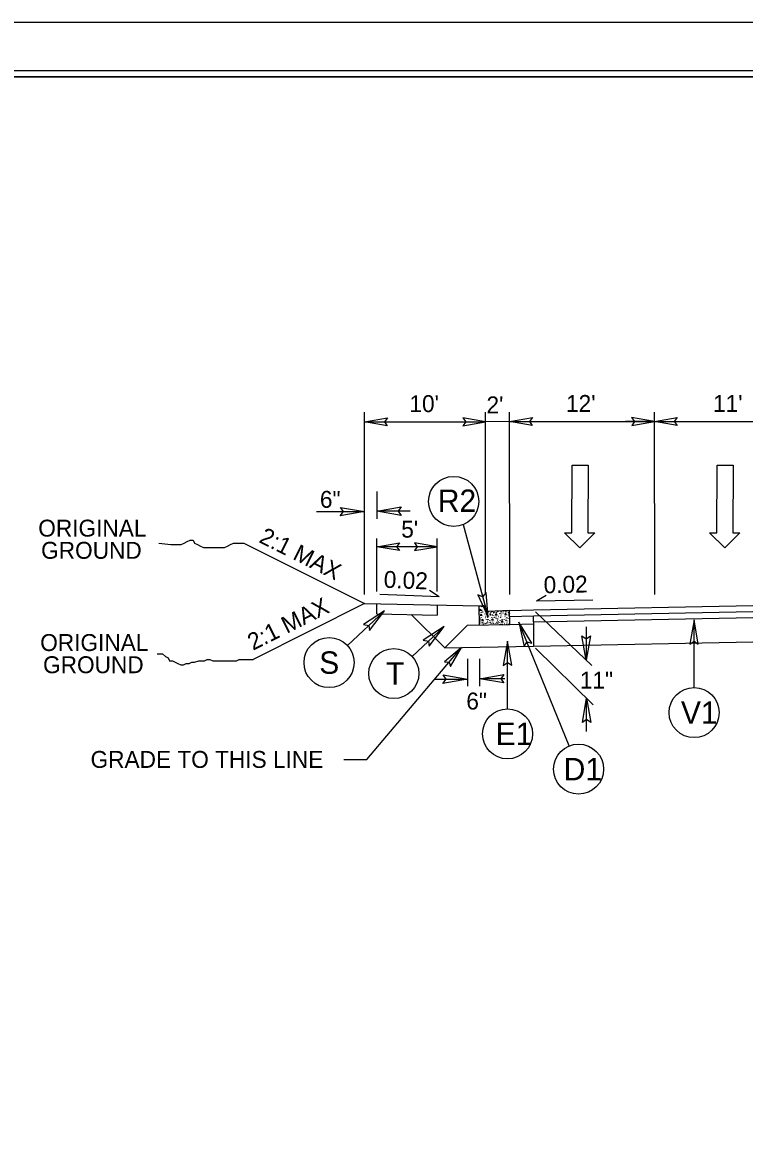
# Model space of a CAD drawing. Extents: x 1640342 to 1730599, y 538663 to 843747.
# Drawn here: x 1729954.3 to 1730014, y 539037.8 to 539130.9 of the extents above; entities that cross this region are included whole.
import ezdxf

# ---------------------------------------------------------------- set-up
doc = ezdxf.new("R2010")
doc.units = 0
for name, color, linetype in [('Default', 7, 'Continuous'), ('Prop Terminator CELL', 7, 'Continuous'), ('Sheet Clip Boundary CELL', 7, 'Continuous'), ('Sheet Layout Plan Border', 7, 'Continuous'), ('Sheet Plan CELL', 7, 'Continuous'), ('Sheet Plan Layout CELL', 7, 'Continuous'), ('Sheet Plot Border Inside CELL', 7, 'Continuous'), ('Sheet Plot Border Outside CELL', 7, 'Continuous'), ('Typical Curb CELL', 7, 'Continuous'), ('Typical Hinge Slope Arterial CELL', 7, 'Continuous'), ('Typical Hinge Slope Interstate CELL', 7, 'Continuous'), ('Typical ID Circle CELL', 7, 'Continuous'), ('Typical Pavement Slope CELL', 7, 'Continuous'), ('Typical Pavement Slope Information CELL', 7, 'Continuous'), ('Typical Shoulder Slope CELL', 7, 'Continuous'), ('Typical Terminator CELL', 7, 'Continuous'), ('Typical Text General CELL', 7, 'Continuous'), ('Typical Text ID Circle CELL', 7, 'Continuous')]:
    doc.layers.add(name, color=color, linetype=linetype)

msp = doc.modelspace()

# ---------------------------------------------------------------- linework, layer by layer
at = {"layer": 'Default'}
for p, q in [((1729982.603, 539083.581), (1729982.603, 539098.671)), ((1729992.603, 539083.581), (1729992.603, 539098.671)), ((1729994.596, 539083.581), (1729994.581, 539098.671)), ((1730006.552, 539098.671), (1730006.567, 539083.593)), ((1729982.603, 539097.882), (1729992.604, 539097.882)), ((1729994.582, 539097.895), (1729992.604, 539097.882)), ((1730006.553, 539097.895), (1730017.553, 539097.906)), ((1729999.724, 539088.703), (1729999.754, 539094.299)), ((1729999.754, 539094.299), (1730001.073, 539094.292)), ((1730001.073, 539094.292), (1730001.043, 539088.696)), ((1730011.71, 539088.703), (1730011.74, 539094.299)), ((1730011.74, 539094.299), (1730013.059, 539094.292)), ((1730013.059, 539094.292), (1730013.029, 539088.696)), ((1729983.603, 539092.116), (1729983.603, 539089.856)), ((1729978.634, 539090.452), (1729982.603, 539090.452)), ((1729986.353, 539090.475), (1729983.603, 539090.475)), ((1729983.603, 539083.835), (1729983.603, 539088.237)), ((1729988.603, 539083.835), (1729988.603, 539088.237)), ((1730000.397, 539087.44), (1729999.125, 539088.706)), ((1729999.125, 539088.706), (1729999.724, 539088.703)), ((1730001.643, 539088.693), (1730000.397, 539087.44)), ((1730001.043, 539088.696), (1730001.643, 539088.693)), ((1730012.382, 539087.44), (1730011.11, 539088.706)), ((1730011.11, 539088.706), (1730011.71, 539088.703)), ((1730013.628, 539088.693), (1730012.382, 539087.44)), ((1730013.029, 539088.696), (1730013.628, 539088.693)), ((1729988.603, 539087.541), (1729983.603, 539087.541)), ((1729996.74, 539082.16), (1730001.395, 539077.704)), ((1730000.926, 539080.902), (1730000.926, 539078.152)), ((1729996.74, 539079.16), (1730001.502, 539074.467)), ((1729991.095, 539078.261), (1729991.095, 539076.001)), ((1729992.095, 539078.261), (1729992.095, 539076.001)), ((1729988.364, 539076.597), (1729991.095, 539076.597)), ((1729994.195, 539076.62), (1729992.095, 539076.62)), ((1730000.95, 539072.261), (1730000.95, 539075.011))]:
    msp.add_line(p, q, dxfattribs=at)
for points in [[(1729984.477, 539097.559), (1729982.603, 539097.882), (1729984.487, 539098.215), (1729984.248, 539097.882)], [(1729990.729, 539097.559), (1729992.604, 539097.882), (1729990.719, 539098.215), (1729990.958, 539097.882)], [(1729996.456, 539097.572), (1729994.582, 539097.895), (1729996.466, 539098.228), (1729996.227, 539097.895)], [(1730004.679, 539097.572), (1730006.553, 539097.895), (1730004.668, 539098.228), (1730004.908, 539097.895)], [(1730008.427, 539097.572), (1730006.553, 539097.895), (1730008.437, 539098.228), (1730008.198, 539097.895)], [(1729985.477, 539087.218), (1729983.603, 539087.541), (1729985.487, 539087.874), (1729985.248, 539087.541)], [(1729986.728, 539087.218), (1729988.603, 539087.541), (1729986.718, 539087.874), (1729986.957, 539087.541)]]:
    msp.add_lwpolyline(points, close=True, dxfattribs=at)
msp.add_lwpolyline([(1729994.582, 539097.895), (1730006.553, 539097.895), (1730004.181, 539097.905)], dxfattribs=at)
at = {"layer": 'Prop Terminator CELL'}
msp.add_lwpolyline([(1729989.693, 539077.625), (1729990.619, 539079.2), (1729989.205, 539078.024), (1729989.598, 539077.993)], close=True, dxfattribs=at)
at = {"layer": 'Sheet Clip Boundary CELL'}
msp.add_lwpolyline([(1729883.99, 538916.418), (1730163.993, 538916.418), (1730163.993, 539084.12), (1730126.14, 539084.12), (1730126.14, 539126.418), (1729883.99, 539126.418)], close=True, dxfattribs=at)
at = {"layer": 'Sheet Layout Plan Border'}
msp.add_lwpolyline([(1729883.99, 538916.418), (1730163.993, 538916.418), (1730163.993, 539084.12), (1730126.14, 539084.12), (1730126.14, 539126.418), (1729883.99, 539126.418)], close=True, dxfattribs=at)
at = {"layer": 'Sheet Plan CELL'}
for points in [[(1729873.99, 538916.418), (1729873.985, 539126.413), (1730133.983, 539126.42), (1730133.985, 539096.408), (1730173.993, 539096.405), (1730173.993, 538916.418)], [(1730173.998, 539126.418), (1729873.99, 539126.418), (1729873.99, 538916.418), (1730173.993, 538916.418)]]:
    msp.add_lwpolyline(points, close=True, dxfattribs=at)
at = {"layer": 'Sheet Plan Layout CELL'}
msp.add_lwpolyline([(1729873.985, 539126.413), (1729873.99, 538916.418), (1730173.99, 538916.418), (1730173.99, 539084.12), (1730126.14, 539084.12), (1730126.14, 539126.418)], close=True, dxfattribs=at)
at = {"layer": 'Sheet Plot Border Inside CELL'}
msp.add_lwpolyline([(1729843.293, 538915.915), (1730176.49, 538915.918), (1730176.493, 539126.915), (1729843.293, 539126.915)], close=True, dxfattribs=at)
at = {"layer": 'Sheet Plot Border Outside CELL'}
msp.add_lwpolyline([(1729840.693, 538911.915), (1730177.393, 538911.915), (1730177.393, 539130.915), (1729840.693, 539130.915)], close=True, dxfattribs=at)
at = {"layer": 'Typical Curb CELL'}
for p, q in [((1729992.071, 539082.657), (1729992.331, 539082.661)), ((1729992.095, 539081.063), (1729992.071, 539082.657)), ((1729992.113, 539082.279), (1729992.266, 539082.326)), ((1729992.251, 539082.236), (1729992.113, 539082.279)), ((1729992.244, 539081.963), (1729992.142, 539081.886)), ((1729992.142, 539081.886), (1729992.308, 539081.849)), ((1729992.308, 539081.849), (1729992.244, 539081.963)), ((1729992.266, 539082.326), (1729992.251, 539082.236)), ((1729992.574, 539082.414), (1729992.574, 539082.425)), ((1729994.574, 539082.279), (1729992.827, 539082.179)), ((1729992.984, 539082.03), (1729992.951, 539081.917)), ((1729992.951, 539081.917), (1729993.071, 539081.912)), ((1729993.071, 539081.912), (1729992.984, 539082.03)), ((1729993.491, 539081.982), (1729993.389, 539081.906)), ((1729993.389, 539081.906), (1729993.555, 539081.869)), ((1729993.555, 539081.869), (1729993.491, 539081.982)), ((1729994.231, 539082.05), (1729994.199, 539081.936)), ((1729994.199, 539081.936), (1729994.32, 539081.931)), ((1729994.32, 539081.931), (1729994.231, 539082.05)), ((1729994.592, 539081.113), (1729994.574, 539082.279)), ((1729992.377, 539081.514), (1729992.275, 539081.437)), ((1729992.275, 539081.437), (1729992.441, 539081.4)), ((1729992.441, 539081.4), (1729992.377, 539081.514)), ((1729993.182, 539081.57), (1729993.08, 539081.493)), ((1729993.08, 539081.493), (1729993.246, 539081.456)), ((1729993.246, 539081.456), (1729993.182, 539081.57)), ((1729993.988, 539081.401), (1729993.886, 539081.325)), ((1729993.886, 539081.325), (1729994.052, 539081.288)), ((1729994.052, 539081.288), (1729993.988, 539081.401))]:
    msp.add_line(p, q, dxfattribs=at)
for centre in [(1729992.086, 539082.547), (1729992.14, 539082.365), (1729992.23, 539081.706), (1729992.241, 539082.094), (1729992.302, 539082.584), (1729992.36, 539082.146), (1729992.4, 539081.748), (1729992.539, 539081.984), (1729992.578, 539081.688), (1729992.616, 539082.179), (1729992.633, 539081.803), (1729992.634, 539082.128), (1729992.665, 539081.958), (1729992.749, 539081.719), (1729992.812, 539082.046), (1729992.839, 539082.148), (1729992.954, 539081.745), (1729993.034, 539082.112), (1729993.114, 539081.679), (1729993.13, 539082.167), (1729993.162, 539081.914), (1729993.24, 539082.075), (1729993.259, 539081.87), (1729993.295, 539082.11), (1729993.314, 539082.013), (1729993.324, 539081.705), (1729993.478, 539081.725), (1729993.489, 539082.113), (1729993.608, 539082.165), (1729993.648, 539081.767), (1729993.787, 539082.003), (1729993.826, 539081.707), (1729993.864, 539082.198), (1729993.881, 539081.822), (1729993.882, 539082.148), (1729993.913, 539081.977), (1729993.997, 539081.739), (1729994.06, 539082.065), (1729994.087, 539082.167), (1729994.202, 539081.765), (1729994.234, 539082.232), (1729994.282, 539082.131), (1729994.362, 539081.699), (1729994.377, 539082.217), (1729994.41, 539081.933), (1729994.488, 539082.094), (1729994.507, 539081.889), (1729994.543, 539082.129), (1729994.562, 539082.033), (1729994.572, 539081.725), (1729992.144, 539081.401), (1729992.199, 539081.545), (1729992.209, 539081.237), (1729992.363, 539081.257), (1729992.409, 539081.145), (1729992.534, 539081.299), (1729992.58, 539081.176), (1729992.672, 539081.535), (1729992.711, 539081.239), (1729992.767, 539081.354), (1729992.798, 539081.508), (1729992.882, 539081.27), (1729992.95, 539081.458), (1729993.004, 539081.601), (1729993.015, 539081.293), (1729993.065, 539081.173), (1729993.169, 539081.313), (1729993.236, 539081.204), (1729993.339, 539081.355), (1729993.449, 539081.173), (1729993.478, 539081.591), (1729993.517, 539081.295), (1729993.572, 539081.41), (1729993.604, 539081.565), (1729993.62, 539081.204), (1729993.688, 539081.326), (1729993.755, 539081.289), (1729993.81, 539081.433), (1729993.821, 539081.125), (1729993.964, 539081.501), (1729993.974, 539081.144), (1729994.135, 539081.532), (1729994.145, 539081.187), (1729994.284, 539081.423), (1729994.302, 539081.566), (1729994.323, 539081.127), (1729994.378, 539081.242), (1729994.41, 539081.396), (1729994.472, 539081.598), (1729994.493, 539081.158)]:
    msp.add_circle(centre, 0.00801, dxfattribs=at)
for centre, start, end in [((1729992.334, 539082.421), 0.8814, 90.8814), ((1729992.813, 539082.418), 180.8814, 273.26586)]:
    msp.add_arc(centre, 0.239, start, end, dxfattribs=at)
at = {"layer": 'Typical Hinge Slope Arterial CELL'}
for p, q in [((1729972.61, 539087.842), (1729982.603, 539082.846)), ((1729982.603, 539082.846), (1729973.386, 539078.223))]:
    msp.add_line(p, q, dxfattribs=at)
msp.add_lwpolyline([(1729965.593, 539087.842), (1729966.577, 539087.72), (1729966.824, 539087.72), (1729967.193, 539087.72), (1729967.439, 539087.72), (1729967.686, 539087.842), (1729967.932, 539087.966), (1729968.178, 539088.089), (1729968.424, 539088.089), (1729968.548, 539087.842), (1729968.794, 539087.72), (1729969.04, 539087.596), (1729969.286, 539087.473), (1729969.533, 539087.473), (1729969.779, 539087.473), (1729970.025, 539087.473), (1729970.271, 539087.473), (1729970.517, 539087.473), (1729970.763, 539087.473), (1729971.01, 539087.473), (1729971.256, 539087.596), (1729971.502, 539087.72), (1729971.748, 539087.842), (1729972.118, 539087.842), (1729972.364, 539087.842), (1729972.61, 539087.842)], dxfattribs=at)
at = {"layer": 'Typical Hinge Slope Interstate CELL'}
msp.add_lwpolyline([(1729965.438, 539078.684), (1729965.668, 539078.684), (1729965.898, 539078.684), (1729966.129, 539078.453), (1729966.359, 539078.338), (1729966.475, 539078.107), (1729966.705, 539078.107), (1729966.935, 539077.993), (1729967.166, 539077.877), (1729967.396, 539077.761), (1729967.626, 539077.761), (1729967.857, 539077.877), (1729968.087, 539077.877), (1729968.317, 539077.993), (1729968.548, 539077.993), (1729968.894, 539078.107), (1729969.124, 539078.107), (1729969.354, 539078.107), (1729969.585, 539078.223), (1729969.815, 539078.223), (1729970.045, 539078.107), (1729970.276, 539078.107), (1729970.506, 539078.107), (1729970.736, 539078.107), (1729970.967, 539078.107), (1729971.313, 539078.107), (1729971.658, 539078.107), (1729972.004, 539078.107), (1729972.234, 539078.223), (1729972.579, 539078.223), (1729972.925, 539078.223), (1729973.386, 539078.223)], dxfattribs=at)
at = {"layer": 'Typical ID Circle CELL'}
for p, q in [((1729990.746, 539089.376), (1729992.818, 539081.709)), ((1729981.173, 539079.369), (1729984.237, 539082.231)), ((1729986.528, 539078.465), (1729989.167, 539080.93)), ((1729999.513, 539071.062), (1729995.356, 539081.294)), ((1730009.84, 539075.888), (1730009.84, 539081.498)), ((1729994.418, 539074.13), (1729994.418, 539079.739))]:
    msp.add_line(p, q, dxfattribs=at)
for centre in [(1729989.964, 539091.293), (1729979.659, 539077.956), (1729985.015, 539077.052), (1730009.84, 539073.817), (1729994.418, 539072.059), (1730000.292, 539069.143)]:
    msp.add_circle(centre, 2.071, dxfattribs=at)
at = {"layer": 'Typical Pavement Slope CELL'}
for p, q in [((1729996.574, 539082.319), (1730024.553, 539082.878)), ((1729986.46, 539081.935), (1729989.224, 539079.172)), ((1729994.574, 539082.279), (1729996.574, 539082.319)), ((1729994.584, 539081.779), (1729996.584, 539081.819)), ((1729996.574, 539081.319), (1730024.563, 539081.878)), ((1729996.574, 539081.319), (1729996.574, 539081.819)), ((1729996.584, 539081.819), (1730024.553, 539082.378)), ((1729991.095, 539081.043), (1729989.224, 539079.172)), ((1729991.095, 539081.043), (1729994.592, 539081.113)), ((1729994.592, 539081.113), (1729996.574, 539081.153)), ((1729996.574, 539079.319), (1730024.553, 539079.878)), ((1729989.224, 539079.172), (1729996.574, 539079.319))]:
    msp.add_line(p, q, dxfattribs=at)
msp.add_lwpolyline([(1729996.574, 539081.319), (1729996.574, 539079.319)], dxfattribs=at)
at = {"layer": 'Typical Pavement Slope Information CELL'}
for p, q in [((1729988.767, 539083.394), (1729983.868, 539083.591)), ((1729988.767, 539083.394), (1729987.954, 539083.908)), ((1729996.813, 539083.056), (1729997.596, 539083.529)), ((1729996.813, 539083.056), (1730001.472, 539083.149))]:
    msp.add_line(p, q, dxfattribs=at)
at = {"layer": 'Typical Shoulder Slope CELL'}
for p, q in [((1729982.603, 539082.846), (1729992.071, 539082.657)), ((1729983.603, 539081.992), (1729983.603, 539082.827)), ((1729988.603, 539082.727), (1729988.603, 539081.892)), ((1729983.603, 539081.992), (1729988.603, 539081.892))]:
    msp.add_line(p, q, dxfattribs=at)
at = {"layer": 'Typical Terminator CELL'}
for p, q in [((1729982.793, 539069.946), (1729990.619, 539079.2)), ((1729980.884, 539069.946), (1729982.793, 539069.946))]:
    msp.add_line(p, q, dxfattribs=at)
for points in [[(1729980.595, 539090.797), (1729982.603, 539090.452), (1729980.584, 539090.095), (1729980.84, 539090.452)], [(1729985.61, 539090.13), (1729983.603, 539090.475), (1729985.622, 539090.832), (1729985.365, 539090.475)], [(1729991.96, 539083.557), (1729992.818, 539081.709), (1729992.636, 539083.751), (1729992.358, 539083.41)], [(1729983.005, 539080.608), (1729984.237, 539082.231), (1729982.518, 539081.114), (1729982.949, 539081.028)], [(1729987.936, 539079.307), (1729989.167, 539080.93), (1729987.448, 539079.813), (1729987.879, 539079.727)], [(1729996.432, 539079.564), (1729995.356, 539081.294), (1729995.785, 539079.289), (1729996.019, 539079.661)], [(1730010.186, 539079.49), (1730009.84, 539081.498), (1730009.484, 539079.479), (1730009.84, 539079.735)], [(1730001.272, 539080.16), (1730000.926, 539078.152), (1730000.569, 539080.171), (1730000.926, 539079.915)], [(1729994.764, 539077.731), (1729994.418, 539079.739), (1729994.061, 539077.72), (1729994.418, 539077.977)], [(1729989.087, 539076.942), (1729991.095, 539076.597), (1729989.076, 539076.24), (1729989.333, 539076.597)], [(1729994.103, 539076.275), (1729992.095, 539076.62), (1729994.114, 539076.977), (1729993.857, 539076.62)], [(1730000.604, 539073.003), (1730000.95, 539075.011), (1730001.307, 539072.992), (1730000.95, 539073.249)]]:
    msp.add_lwpolyline(points, close=True, dxfattribs=at)

# ---------------------------------------------------------------- texts
at = {"layer": 'Default'}
for s, p in [("10'", (1729986.304, 539098.682)), ('6"', (1729978.904, 539090.763)), ('ORIGINAL', (1729955.617, 539088.381)), ('GROUND', (1729955.852, 539086.545)), ('ORIGINAL', (1729955.778, 539078.915)), ('GROUND', (1729956.013, 539077.08)), ('11"', (1730000.393, 539075.802)), ('6"', (1729991.007, 539074.075))]:
    msp.add_text(s, height=1.4, dxfattribs=at).set_placement(p)
msp.add_text("5'", height=1.4, rotation=360, dxfattribs=at).set_placement((1729985.627, 539088.296))
at = {"layer": 'Typical Hinge Slope Interstate CELL'}
for rotation, p in [(333.43542, (1729973.779, 539087.945)), (26.56458, (1729973.37, 539078.934))]:
    msp.add_text('2:1 MAX', height=1.4, rotation=rotation, dxfattribs=at).set_placement(p)
at = {"layer": 'Typical Pavement Slope Information CELL'}
for s, p in [("2'", (1729992.677, 539098.578)), ("12'", (1729999.252, 539098.695)), ("11'", (1730011.405, 539098.701))]:
    msp.add_text(s, height=1.4, dxfattribs=at).set_placement(p)
for rotation, p in [(357.69972, (1729984.158, 539084.153)), (1.14574, (1729997.412, 539083.69))]:
    msp.add_text('0.02', height=1.4, rotation=rotation, dxfattribs=at).set_placement(p)
at = {"layer": 'Typical Text General CELL'}
msp.add_text('GRADE TO THIS LINE', height=1.4, dxfattribs=at).set_placement((1729959.941, 539069.246))
at = {"layer": 'Typical Text ID Circle CELL'}
for s, height, p in [('R2', 1.8535, (1729988.652, 539090.424)), ('S', 1.854, (1729978.848, 539077.029)), ('T', 1.854, (1729984.372, 539076.125)), ('V1', 1.8535, (1730008.752, 539072.891)), ('E1', 1.8535, (1729993.434, 539071.132)), ('D1', 1.8535, (1729999.057, 539068.216))]:
    msp.add_text(s, height=height, dxfattribs=at).set_placement(p)

doc.saveas('drawing.dxf')
